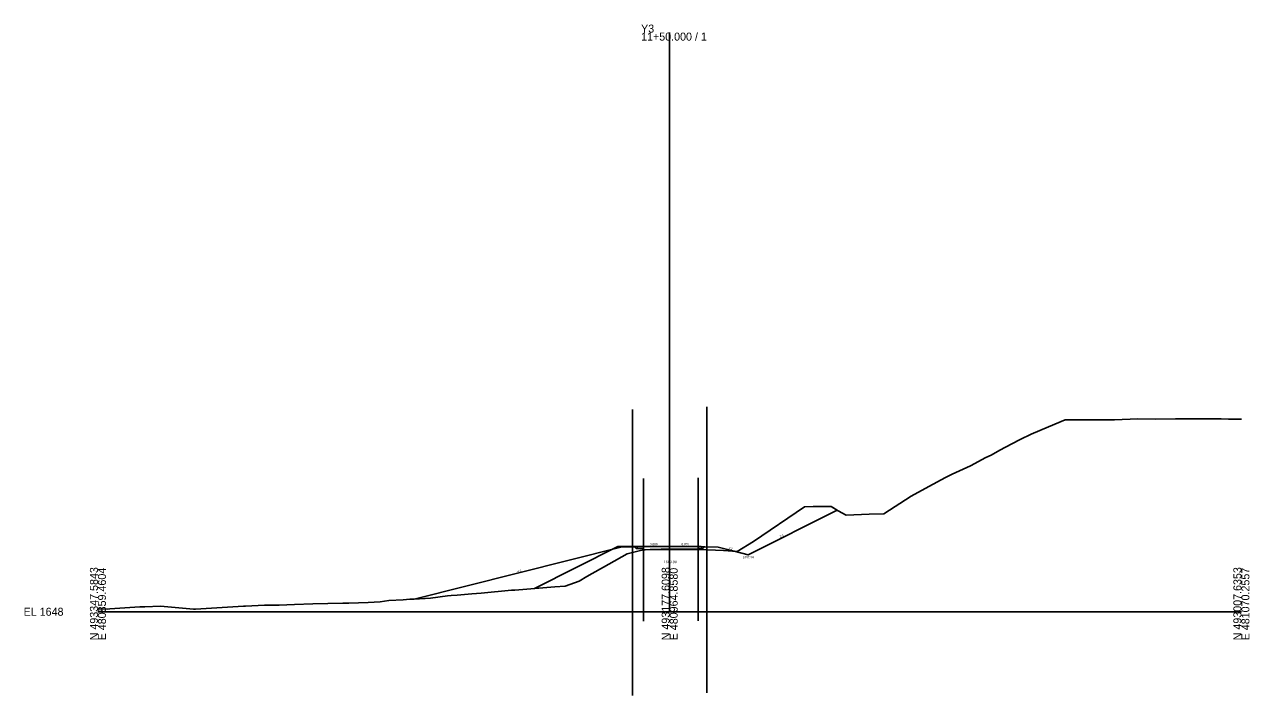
# Model space of a CAD drawing. Extents: x -26 to 481018, y -48 to 493233.
# Drawn here: x -25.7 to 402.8, y 1470.7 to 1705.4 of the extents above; entities that cross this region are included whole.
import ezdxf

# ---------------------------------------------------------------- set-up
doc = ezdxf.new("R2010")
doc.units = 0
for name, color, linetype in [('Exist Cross Section Cell', 7, 'Continuous'), ('Exist XS Center Line Elevation Label', 7, 'Continuous'), ('Exist XS Ground Line', 7, 'Continuous'), ('Prop XS Ditch Slope Text', 7, 'Continuous'), ('Prop XS Ditch Standard Text', 7, 'Continuous'), ('Prop XS Dump Level', 7, 'Continuous'), ('Prop XS Earthwork Shape', 7, 'Continuous'), ('Prop XS Finish Grade', 7, 'Continuous'), ('Prop XS Finish Grade Earthwork', 7, 'Continuous'), ('Prop XS Finish Grade Pavement', 7, 'Continuous'), ('Prop XS Pvmt Edge Slope', 7, 'Continuous'), ('Prop XS SE Text', 7, 'Continuous'), ('Prop XS Shoulder Borrow Shape', 7, 'Continuous'), ('Prop XS Side Slope Text', 7, 'Continuous'), ('Prop XS Subgrade Earthwork', 7, 'Continuous'), ('Scratch_Level_1', 7, 'Continuous'), ('Scratch_Level_2', 7, 'Continuous'), ('Scratch_Level_4', 7, 'Continuous'), ('Scratch_Level_5', 7, 'Continuous')]:
    doc.layers.add(name, color=color, linetype=linetype)

msp = doc.modelspace()

# ---------------------------------------------------------------- linework, layer by layer
at = {"layer": 'Exist Cross Section Cell'}
for p, q in [((200, 1500), (200, 1702.6)), ((0, 1500), (200, 1500)), ((200, 1500), (400, 1500))]:
    msp.add_line(p, q, dxfattribs=at)
at = {"layer": 'Exist XS Ground Line'}
for p, q in [((326.48, 1562.11), (332.47, 1564.7)), ((332.47, 1564.7), (338.33, 1567.1)), ((338.33, 1567.1), (339.05, 1567.12)), ((339.05, 1567.12), (346.03, 1567.14)), ((346.03, 1567.14), (351.22, 1567.19)), ((351.22, 1567.19), (355.56, 1567.18)), ((355.56, 1567.18), (363.81, 1567.48)), ((363.81, 1567.48), (369.97, 1567.4)), ((369.97, 1567.4), (376.93, 1567.5)), ((376.93, 1567.5), (384.87, 1567.53)), ((384.87, 1567.53), (391.41, 1567.5)), ((391.41, 1567.5), (392.36, 1567.48)), ((392.36, 1567.48), (392.96, 1567.49)), ((392.96, 1567.49), (395.49, 1567.42)), ((395.49, 1567.42), (400, 1567.33)), ((319.72, 1558.77), (322.59, 1560.27)), ((322.59, 1560.27), (326.48, 1562.11)), ((312.46, 1554.76), (315.49, 1556.5)), ((315.49, 1556.5), (319.72, 1558.77)), ((305.19, 1551.04), (310.58, 1554.01)), ((310.58, 1554.01), (312.46, 1554.76)), ((296.51, 1546.94), (297.93, 1547.61)), ((297.93, 1547.61), (298.81, 1548.12)), ((298.81, 1548.12), (305.19, 1551.04)), ((284.45, 1540.43), (290.66, 1543.86)), ((290.66, 1543.86), (296.51, 1546.94)), ((274.87, 1534.29), (284.45, 1540.43)), ((229.3, 1524.62), (247.14, 1536.72)), ((247.14, 1536.72), (250.18, 1536.8)), ((250.18, 1536.8), (256.53, 1536.84)), ((256.53, 1536.84), (259, 1535.25)), ((259, 1535.25), (261.78, 1533.84)), ((269.84, 1534.13), (274.87, 1534.29)), ((261.78, 1533.84), (269.84, 1534.13)), ((185.15, 1520.24), (189.36, 1521.3)), ((189.36, 1521.3), (190.82, 1521.67)), ((190.82, 1521.67), (191.47, 1521.69)), ((191.47, 1521.69), (193.13, 1521.74)), ((193.13, 1521.74), (194.35, 1521.78)), ((194.35, 1521.78), (194.78, 1521.79)), ((194.78, 1521.79), (197, 1521.84)), ((197, 1521.84), (197.97, 1521.86)), ((197.97, 1521.86), (199.75, 1521.91)), ((199.75, 1521.91), (200.63, 1521.9)), ((200.63, 1521.9), (202.85, 1521.9)), ((202.85, 1521.9), (204.22, 1521.9)), ((204.22, 1521.9), (205.21, 1521.89)), ((205.21, 1521.89), (205.81, 1521.89)), ((205.81, 1521.89), (207.01, 1521.88)), ((207.01, 1521.88), (208.85, 1521.84)), ((208.85, 1521.84), (209.92, 1521.84)), ((209.92, 1521.84), (210.43, 1521.81)), ((210.43, 1521.81), (218.83, 1521.39)), ((218.83, 1521.39), (223.66, 1521.09)), ((223.66, 1521.09), (229.3, 1524.62)), ((178.74, 1516.61), (185.15, 1520.24)), ((171.04, 1512.3), (178.74, 1516.61)), ((145.81, 1507.59), (159.8, 1508.77)), ((159.8, 1508.77), (163.39, 1508.93)), ((163.39, 1508.93), (168.38, 1510.67)), ((168.38, 1510.67), (171.04, 1512.3)), ((101.79, 1503.89), (106.72, 1504.21)), ((106.72, 1504.21), (109.06, 1504.41)), ((109.06, 1504.41), (110.51, 1504.45)), ((110.51, 1504.45), (116.32, 1504.81)), ((116.32, 1504.81), (122.28, 1505.56)), ((122.28, 1505.56), (123.59, 1505.68)), ((123.59, 1505.68), (125.7, 1505.85)), ((125.7, 1505.85), (130.85, 1506.25)), ((130.85, 1506.25), (134.04, 1506.52)), ((134.04, 1506.52), (144.68, 1507.5)), ((144.68, 1507.5), (145.81, 1507.59)), ((0, 1501.03), (3.29, 1500.96)), ((3.29, 1500.96), (4.14, 1501)), ((4.14, 1501), (14.62, 1501.76)), ((14.62, 1501.76), (16.36, 1501.77)), ((16.36, 1501.77), (21.89, 1501.93)), ((21.89, 1501.93), (33.46, 1500.91)), ((33.46, 1500.91), (34.07, 1500.95)), ((34.07, 1500.95), (50.94, 1501.92)), ((50.94, 1501.92), (51.66, 1501.94)), ((51.66, 1501.94), (58.21, 1502.31)), ((58.21, 1502.31), (63.43, 1502.32)), ((63.43, 1502.32), (68.76, 1502.52)), ((68.76, 1502.52), (75.2, 1502.74)), ((75.2, 1502.74), (85.72, 1503.01)), ((85.72, 1503.01), (86.97, 1503.02)), ((86.97, 1503.02), (87.74, 1503.05)), ((87.74, 1503.05), (94.53, 1503.18)), ((94.53, 1503.18), (98.74, 1503.49)), ((98.74, 1503.49), (101.79, 1503.89))]:
    msp.add_line(p, q, dxfattribs=at)
at = {"layer": 'Prop XS Dump Level'}
for p, q in [((189, 1522.78), (200, 1522.78)), ((200, 1522.78), (211, 1522.78))]:
    msp.add_line(p, q, dxfattribs=at)
at = {"layer": 'Prop XS Earthwork Shape'}
for points in [[(227.42, 1519.94), (258.58, 1535.52), (256.53, 1536.84), (250.18, 1536.8), (247.14, 1536.72), (229.3, 1524.62), (223.66, 1521.09), (222.54, 1521.16)], [(187.71, 1522.73), (188.31, 1522.13), (188.96, 1522.16), (190.82, 1522.16), (190.82, 1521.66), (189.36, 1521.3), (185.15, 1520.24), (178.74, 1516.61), (171.04, 1512.3), (168.38, 1510.67), (163.39, 1508.93), (159.8, 1508.77), (145.81, 1507.59), (144.68, 1507.5), (134.04, 1506.52), (130.85, 1506.25), (125.7, 1505.85), (123.59, 1505.68), (122.28, 1505.56), (116.32, 1504.81), (110.61, 1504.46), (182.96, 1522.54)], [(211.03, 1522.16), (211.61, 1522.13), (212.22, 1522.74), (217, 1522.55), (222.54, 1521.16), (218.83, 1521.39), (210.43, 1521.81), (209.92, 1521.84), (209.92, 1522.16)]]:
    msp.add_lwpolyline(points, close=True, dxfattribs=at)
at = {"layer": 'Prop XS Finish Grade'}
for p, q in [((188.96, 1522.78), (187.71, 1522.73)), ((210.96, 1522.78), (212.22, 1522.74))]:
    msp.add_line(p, q, dxfattribs=at)
at = {"layer": 'Prop XS Finish Grade Earthwork'}
for p, q in [((227.42, 1519.94), (258.58, 1535.52)), ((182.96, 1522.54), (110.61, 1504.46)), ((182.96, 1522.54), (187.71, 1522.73)), ((212.22, 1522.74), (217, 1522.55)), ((217, 1522.55), (227.42, 1519.94))]:
    msp.add_line(p, q, dxfattribs=at)
at = {"layer": 'Prop XS Finish Grade Pavement'}
for p, q in [((188.96, 1522.78), (199.96, 1522.78)), ((199.96, 1522.78), (210.96, 1522.78))]:
    msp.add_line(p, q, dxfattribs=at)
at = {"layer": 'Prop XS Pvmt Edge Slope'}
for p, q in [((188.96, 1522.78), (188.31, 1522.13)), ((210.96, 1522.78), (211.61, 1522.13))]:
    msp.add_line(p, q, dxfattribs=at)
at = {"layer": 'Prop XS Shoulder Borrow Shape'}
for points in [[(188.96, 1522.78), (187.71, 1522.73), (188.31, 1522.13)], [(187.71, 1522.73), (188.31, 1522.13), (188.96, 1522.78)], [(187.71, 1522.73), (188.31, 1522.13), (188.96, 1522.78)], [(187.71, 1522.73), (188.31, 1522.13), (188.96, 1522.78)], [(210.96, 1522.78), (212.22, 1522.74), (211.61, 1522.13)], [(212.22, 1522.74), (211.61, 1522.13), (210.96, 1522.78)], [(212.22, 1522.74), (211.61, 1522.13), (210.96, 1522.78)], [(212.22, 1522.74), (211.61, 1522.13), (210.96, 1522.78)]]:
    msp.add_lwpolyline(points, close=True, dxfattribs=at)
at = {"layer": 'Prop XS Subgrade Earthwork'}
for p, q in [((187.71, 1522.73), (188.31, 1522.13)), ((188.96, 1522.16), (188.31, 1522.13)), ((190.82, 1522.16), (188.96, 1522.16)), ((190.82, 1522.16), (190.82, 1521.66)), ((209.92, 1522.16), (211.03, 1522.16)), ((209.92, 1522.16), (209.92, 1521.84)), ((211.03, 1522.16), (211.61, 1522.13)), ((212.22, 1522.74), (211.61, 1522.13))]:
    msp.add_line(p, q, dxfattribs=at)
at = {"layer": 'Scratch_Level_1'}
for p, q in [((190.82, 1546.67), (190.82, 1496.67)), ((190.82, 1546.67), (190.82, 1496.67)), ((209.92, 1546.84), (209.92, 1496.84)), ((209.92, 1546.84), (209.92, 1496.84))]:
    msp.add_line(p, q, dxfattribs=at)
at = {"layer": 'Scratch_Level_2'}
for p, q in [((181.9, 1522.78), (152.67, 1508.17)), ((188.9, 1522.78), (181.9, 1522.78))]:
    msp.add_line(p, q, dxfattribs=at)
at = {"layer": 'Scratch_Level_4'}
msp.add_line((190.78, 1521.66), (210.96, 1521.78), dxfattribs=at)
at = {"layer": 'Scratch_Level_5'}
for p, q in [((187, 1570.7), (187, 1470.7)), ((187, 1570.7), (187, 1470.7)), ((213, 1571.68), (213, 1471.68))]:
    msp.add_line(p, q, dxfattribs=at)

# ---------------------------------------------------------------- texts
at = {"layer": 'Exist Cross Section Cell'}
for s, p in [('Y3', (190, 1702.6)), ('11+50.000 / 1', (190, 1699.8)), ('EL 1648', (-26, 1498.6))]:
    msp.add_text(s, height=2.8, dxfattribs=at).set_placement(p)
for s, p in [('N 493347.5843', (0, 1490)), ('E 480859.4604', (2.8, 1490)), ('N 493177.6098', (200, 1490)), ('E 480964.8580', (202.8, 1490)), ('N 493007.6353', (400, 1490)), ('E 481070.2557', (402.8, 1490))]:
    msp.add_text(s, height=2.8, rotation=90, dxfattribs=at).set_placement(p)
at = {"layer": 'Exist XS Center Line Elevation Label'}
msp.add_text('1669.90', height=0.9, dxfattribs=at).set_placement((197.99, 1517))
at = {"layer": 'Prop XS Ditch Slope Text'}
msp.add_text('4:1', height=0.75, rotation=345.9638, dxfattribs=at).set_placement((220.58, 1521.99))
at = {"layer": 'Prop XS Ditch Standard Text'}
msp.add_text('1667.94', height=0.75, dxfattribs=at).set_placement((225.63, 1518.74))
at = {"layer": 'Prop XS Dump Level'}
for p in [(184, 1522.54), (216, 1522.54)]:
    msp.add_text('Case2', height=0.04, dxfattribs=at).set_placement(p)
at = {"layer": 'Prop XS SE Text'}
msp.add_text('0.000', height=0.75, dxfattribs=at).set_placement((193.14, 1523.29))
msp.add_text('0.000', height=0.75, rotation=360, dxfattribs=at).set_placement((204.14, 1523.29))
at = {"layer": 'Prop XS Side Slope Text'}
for s, rotation, p in [('2:1', 26.5651, (238.69, 1525.91)), ('4:1', 14.0362, (146.81, 1513.72))]:
    msp.add_text(s, height=0.75, rotation=rotation, dxfattribs=at).set_placement(p)

doc.saveas('drawing.dxf')
